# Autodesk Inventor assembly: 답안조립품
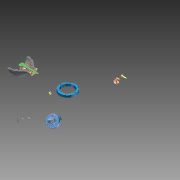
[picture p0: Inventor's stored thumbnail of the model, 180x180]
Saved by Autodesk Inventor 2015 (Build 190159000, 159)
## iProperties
Created: 2026-05
Part Number: 답안조립품
Document SubType Name: Assembly
Designer: 104
Author: 104
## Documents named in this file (19)
- C:\Users\104\Desktop\새 폴더\답안조립품.iam
- C:\Users\104\Documents\Inventor\6각 구멍붙이 볼트 M4x10.ipt
- C:\Users\104\Desktop\새 폴더\가져온 구성요소\6각 구멍붙이 볼트 M4x20\6각 구멍붙이 볼트 M4x20.ipt
- C:\Users\104\Desktop\새 폴더\가져온 구성요소\6각 구멍붙이 볼트 M6x10\6각 구멍붙이 볼트 M6x10.ipt
- C:\Users\104\Desktop\새 폴더\가져온 구성요소\깊은 홈 볼 베어링 6010\깊은 홈 볼 베어링 6010.ipt
- C:\Users\104\Desktop\새 폴더\가져온 구성요소\깊은 홈 볼 베어링 6203\깊은 홈 볼 베어링 6203.ipt
- C:\Users\104\Desktop\새 폴더\가져온 구성요소\깊은 홈 볼 베어링 6900\깊은 홈 볼 베어링 6900.ipt
- C:\Users\104\Desktop\새 폴더\가져온 구성요소\링 기어\링 기어.ipt
- C:\Users\104\Desktop\새 폴더\가져온 구성요소\선 기어 축\선 기어 축.ipt
- C:\Users\104\Desktop\새 폴더\가져온 구성요소\엔드 캡\엔드 캡.ipt
- C:\Users\104\Desktop\새 폴더\가져온 구성요소\오일 실 17 32 8\오일 실 17 32 8.ipt
- C:\Users\104\Desktop\새 폴더\가져온 구성요소\유성 기어\유성 기어.ipt
- C:\Users\104\Desktop\새 폴더\가져온 구성요소\유성 축\유성 축.ipt
- C:\Users\104\Desktop\새 폴더\가져온 구성요소\유성 캐리어 커버\유성 캐리어 커버.ipt
- C:\Users\104\Desktop\새 폴더\가져온 구성요소\유성 캐리어\유성 캐리어.ipt
- C:\Users\104\Desktop\새 폴더\가져온 구성요소\축용 C형 멈춤링 17\축용 C형 멈춤링 17.ipt
- C:\Users\104\Desktop\새 폴더\가져온 구성요소\칼라\칼라.ipt
- C:\Users\104\Desktop\새 폴더\가져온 구성요소\커버\커버.ipt
- C:\Users\104\Desktop\새 폴더\본체.ipt
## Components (3 placed, 3 different names)
1. 6각 구멍붙이 볼트 M4x10:1
2. 6각 구멍붙이 볼트 M4x20:1
3. 6각 구멍붙이 볼트 M6x10:1
